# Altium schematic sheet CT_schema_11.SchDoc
size 385 x 278 mm
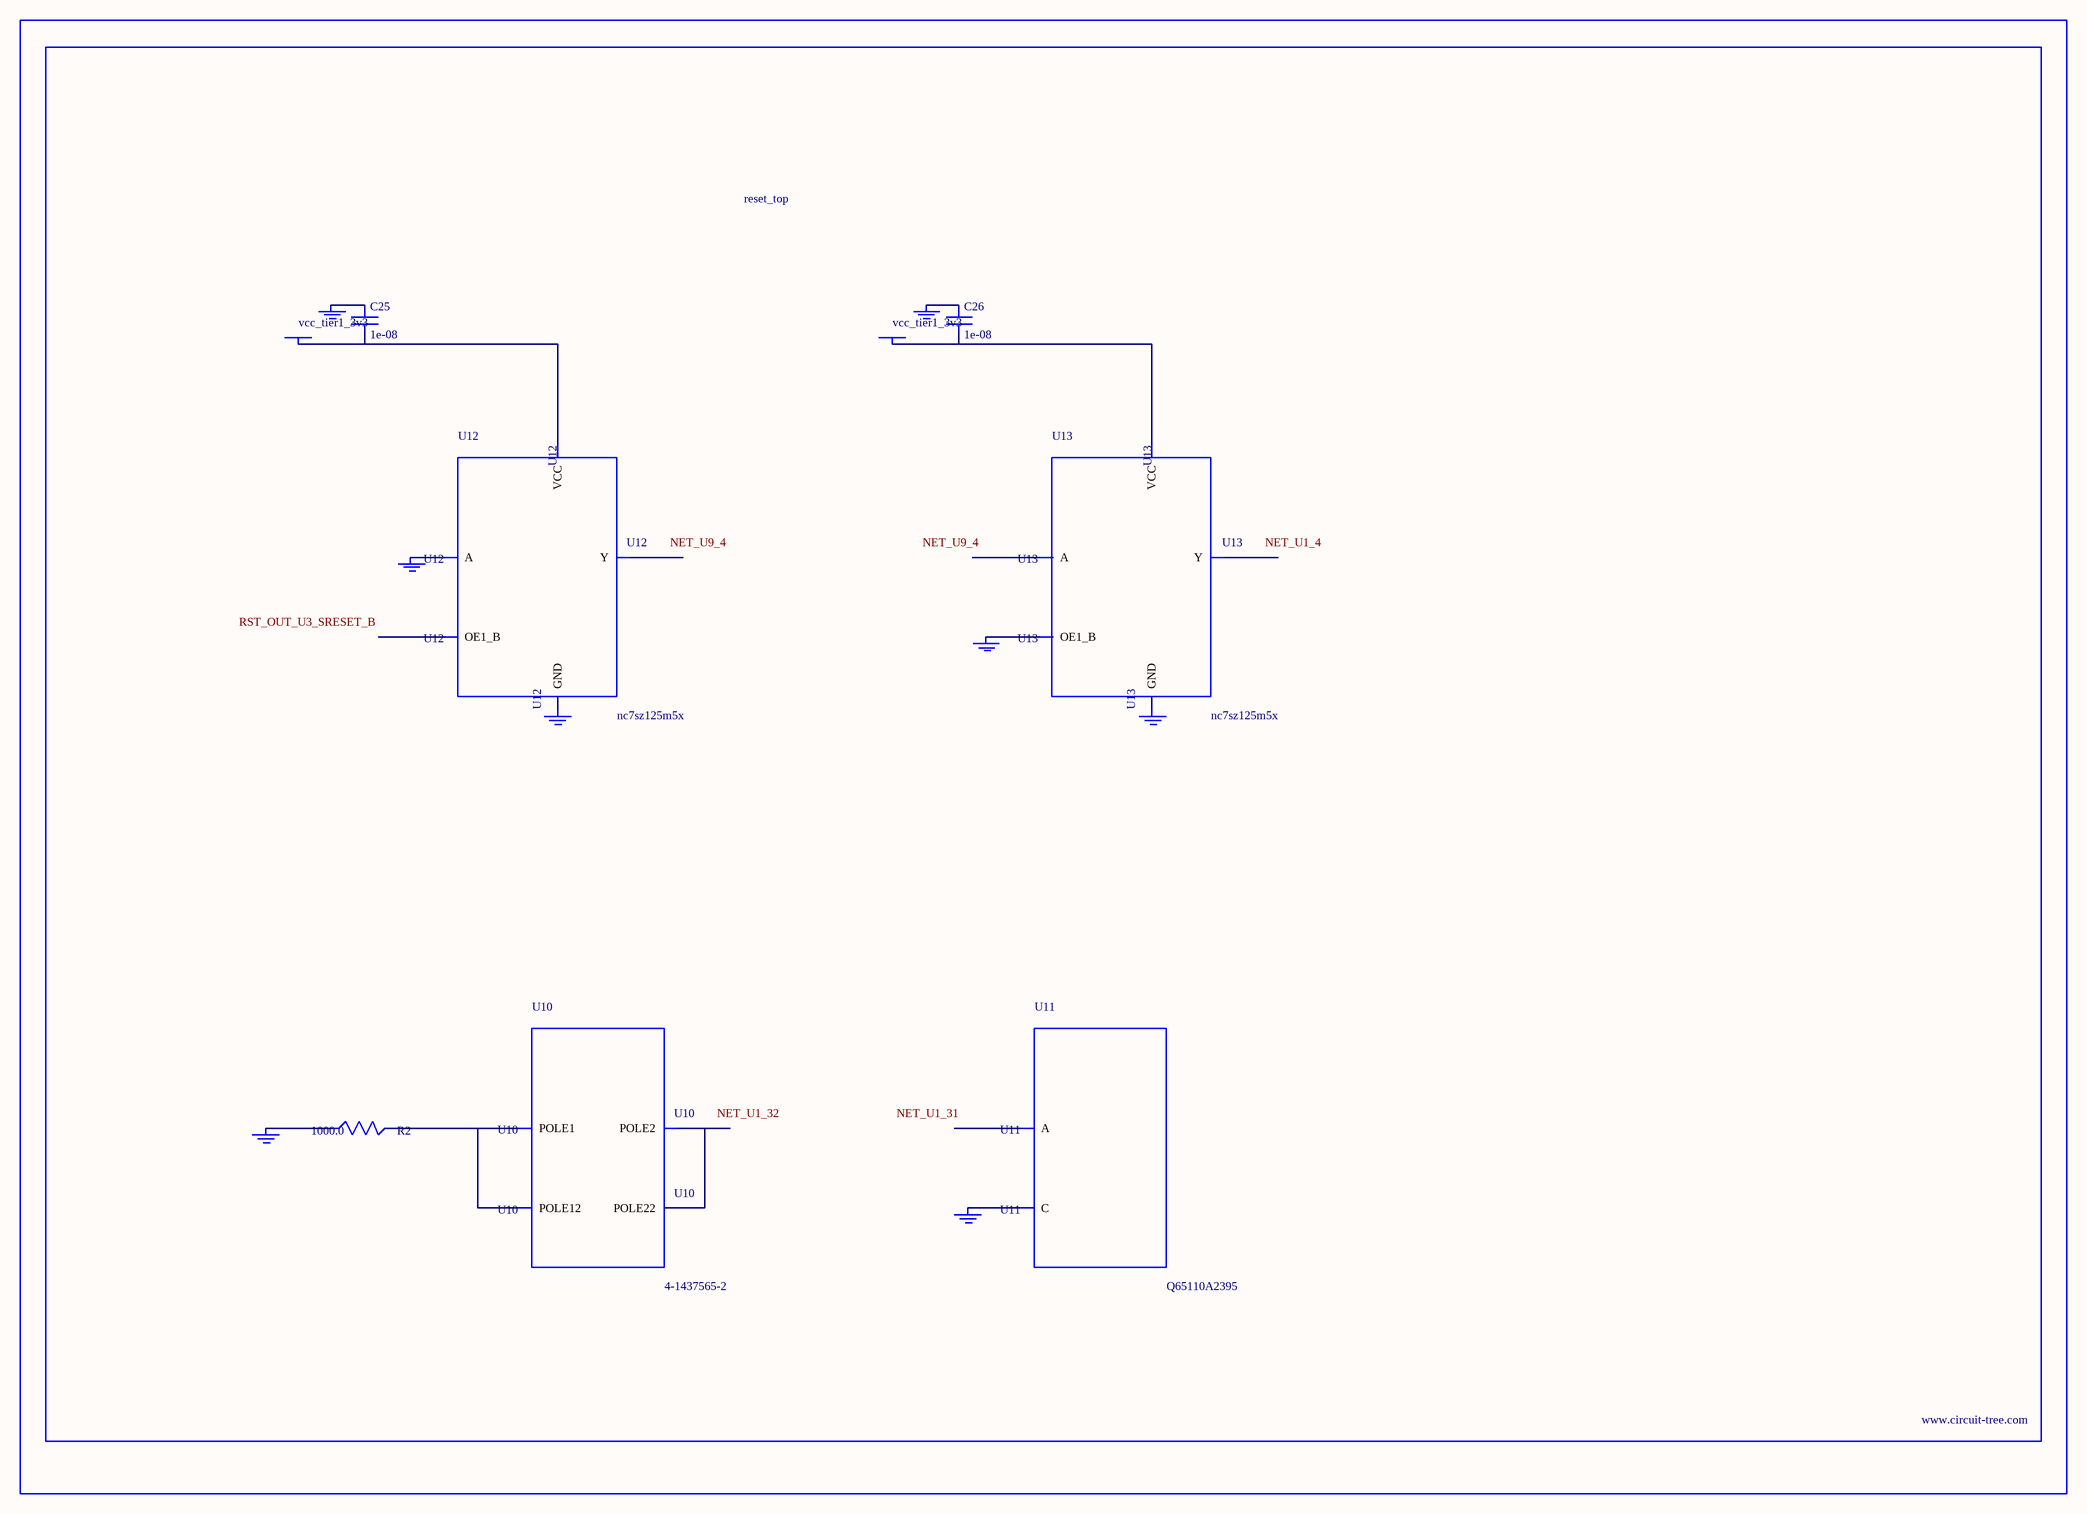
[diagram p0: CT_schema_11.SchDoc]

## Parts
BORDER10  (no value)
C25  1e-08  [C0402]
C26  1e-08  [C0402]
GND_INSTANCE_10_0  (no value)
GND_INSTANCE_10_1  (no value)
GND_INSTANCE_10_2  (no value)
GND_INSTANCE_10_3  (no value)
GND_INSTANCE_10_4  (no value)
GND_INSTANCE_10_5  (no value)
GND_INSTANCE_10_6  (no value)
GND_INSTANCE_10_7  (no value)
POWER_INSTANCE_10_0  vcc_tier1_3v3
POWER_INSTANCE_10_1  vcc_tier1_3v3
R2  1000.0  [R0603]
U10  4-1437565-2  [SW_4-1437565-2]
U11  Q65110A2395  [LGM67K-G1J2-24-Z]
U12  nc7sz125m5x  [NC7SZ125M5X]
U13  nc7sz125m5x  [NC7SZ125M5X]

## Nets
NetC25_1: C25.1 GND_INSTANCE_10_2.0(GND)
NetC25_2: C25.2 POWER_INSTANCE_10_0.0(PWR) U12.5(VCC)
NetC26_1: C26.1 GND_INSTANCE_10_5.0(GND)
NetC26_2: C26.2 POWER_INSTANCE_10_1.0(PWR) U13.5(VCC)
NetGND_INSTANCE_10_0_0: GND_INSTANCE_10_0.0(GND) R2.1
NetGND_INSTANCE_10_1_0: GND_INSTANCE_10_1.0(GND) U11.C
NetGND_INSTANCE_10_3_0: GND_INSTANCE_10_3.0(GND) U12.2(A)
NetGND_INSTANCE_10_4_0: GND_INSTANCE_10_4.0(GND) U12.3(GND)
NetGND_INSTANCE_10_6_0: GND_INSTANCE_10_6.0(GND) U13.1(OE1_B)
NetGND_INSTANCE_10_7_0: GND_INSTANCE_10_7.0(GND) U13.3(GND)
NetR2_2: R2.2 U10.1(POLE1) U10.2(POLE12)
NetU10_3: U10.3(POLE2) U10.4(POLE22)

Not connected (* = marked no-connect by the designer): U11 A; U12 1(OE1_B) 4(Y); U13 2(A) 4(Y)

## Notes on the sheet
- Labels drawn without touching a wire or pin: NET_U1_4, NET_U1_31, NET_U1_32, NET_U9_4, RST_OUT_U3_SRESET_B

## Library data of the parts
BORDER10 = BORDER_PAGE10
C25 C26 = C0402C103K3RAC
GND_INSTANCE_10_0-GND_INSTANCE_10_7 = GND
POWER_INSTANCE_10_0 POWER_INSTANCE_10_1 = PWR
R2 = RC0603JR-071KL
